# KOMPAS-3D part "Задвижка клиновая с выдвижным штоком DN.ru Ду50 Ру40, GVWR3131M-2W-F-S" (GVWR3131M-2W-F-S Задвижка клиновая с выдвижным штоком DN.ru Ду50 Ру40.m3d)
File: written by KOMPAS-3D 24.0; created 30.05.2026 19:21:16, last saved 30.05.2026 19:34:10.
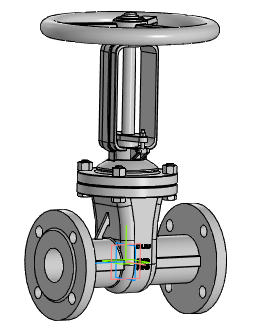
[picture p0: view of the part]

Document properties: Автор: R2D2; Полное имя файла: E:\Работа\Зайцев\GVWR3131M-2W-F-S Задвижка клиновая с выдвижным штоком DN.ru Ду50-100 Ру40\исходные материалы\DN50\GVWR3131M-2W-F-S Задвижка клиновая с выдвижным штоком DN.ru Ду50 Ру40.m3d

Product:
- Component [detail]: Деталь2  | qty 1  | pos. 1  | Автор: R2D2; additional columns: Типовые; source file: Деталь2 Деталь2.m3d
- Component [detail]: AS 1110 - M12 x 45  | qty 4  | pos. 2  | Комментарий: Болты и винты   шестигранные точные   метрические ISO; Автор: R2D2; additional columns: Сталь, мягкая; source file: AS 1110 - M12 x 45 AS 1110 - M12 x 45.m3d
- Component [detail]: ANSI B18.2.4.2M - M12x1,75 - 18  | designation ANSI B18.2.4.2M - M12x1,75  | qty 4  | pos. 3  | Комментарий: Типы метрических   шестигранных гаек   2; Автор: R2D2; additional columns: Сталь, мягкая; source file: ANSI B18.2.4.2M - M12x1,75 ANSI B18.2.4.2M - M12x1,75 - 18.m3d
- Component [detail]: ANSI B18.2.4.2M - M5x0,8 - 8  | designation ANSI B18.2.4.2M - M5x0,8  | qty 1  | pos. 4  | Комментарий: Типы метрических   шестигранных гаек   2; Автор: R2D2; additional columns: Сталь, мягкая; source file: ANSI B18.2.4.2M - M5x0,8 ANSI B18.2.4.2M - M5x0,8 - 8.m3d
- Component [detail]: Деталь1  | qty 1  | pos. 5  | Автор: R2D2; additional columns: Типовые; source file: 2.m3d
- Component [detail]: ФЛАНЕЦ  | designation Деталь1  | qty 1  | pos. 5  | Автор: R2D2; additional columns: Типовые; source file: 1.m3d
- Component [detail]: ФЛАНЕЦ  | designation Деталь1-01  | qty 1  | pos. 6  | Автор: R2D2; additional columns: Типовые; source file: 1.m3d
- Component [detail]: ANSI B18.2.4.2M - M5x0,8 - 8  | designation ANSI B18.2.4.2M - M5x0,8-01  | qty 1  | pos. 7  | Комментарий: Типы метрических   шестигранных гаек   2; Автор: R2D2; additional columns: Сталь, мягкая; source file: ANSI B18.2.4.2M - M5x0,8 ANSI B18.2.4.2M - M5x0,8 - 8.m3d
- Component [detail]: Деталь1  | qty 1  | Автор: R2D2; additional columns: Типовые; source file: 3.m3d
- Body: Тело 1  | qty 1
    Масса: 23.339168
- Part/product: Задвижка клиновая с выдвижным штоком DN.ru Ду50 Ру40  | designation GVWR3131M-2W-F-S
    Масса: 12
    Раздел спецификации: Прочие изделия
    Примечание: D040-08605

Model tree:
1. Массив по концентрической сетке:1  (labels: Грань.Твердое тело1)  (4 pattern instances)
     Шаг 2 = 360
2. Элемент выдавливания:1  (with: Грань.Элемент выдавливания:1, Грань.Элемент вращения:1)
     Расстояние 1 = 42.9933
3. Элемент выдавливания:2  (with: Грань.Элемент выдавливания:1, Грань.Элемент вращения:1)
     Расстояние 1 = 44.6136
4. Элемент выдавливания:3  (with: Грань.Элемент выдавливания:1)
     Расстояние 1 = 54.75
5. Эскиз:1
6. Элемент выдавливания:4  (with: Грань.Элемент выдавливания:1, Грань.Элемент вращения:1)  (labels: Грань.Твердое тело1; Грань.Solid1; Твердое тело1)
     Расстояние 1 = 46; Смещение 1 = 1; Расстояние = -125; Ориентация = 2; Ориентация = 2; Расстояние = -362.5

Referenced files in E:\Работа\Зайцев\GVWR3131M-2W-F-S Задвижка клиновая с выдвижным штоком DN.ru Ду50-100 Ру40\исходные материалы\DN50\: Деталь2 Деталь2.m3d, AS 1110 - M12 x 45 AS 1110 - M12 x 45.m3d, ANSI B18.2.4.2M - M12x1,75 ANSI B18.2.4.2M - M12x1,75 - 18.m3d, ANSI B18.2.4.2M - M5x0,8 ANSI B18.2.4.2M - M5x0,8 - 8.m3d, 2.m3d, 1.m3d, 3.m3d
Referenced files in E:\Работа\Зайцев\GVWR3131M-2W-F-S Задвижка клиновая с выдвижным штоком DN.ru Ду50-200 Ру63\DN50\исходные материалы\: ANSI B18.2.4.2M - M12x1,75 ANSI B18.2.4.2M - M12x1,75 - 18.m3d, AS 1110 - M12 x 45 AS 1110 - M12 x 45.m3d
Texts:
  GVWR3131M-2W-F-S
  DN50
  GOST 26.020 Pr3
  PN40
  Деталь2 Деталь2
  AS 1110 - M12 x 45 AS 1110 - M12 x 45 (1)
  ANSI B18.2.4.2M - M12x1,75 ANSI B18.2.4.2M - M12x1,75 - 18 (1)
  ANSI B18.2.4.2M - M5x0,8 ANSI B18.2.4.2M - M5x0,8 - 8
  Деталь1 Деталь1
  Деталь1 ФЛАНЕЦ
  Деталь1-01 ФЛАНЕЦ
  ANSI B18.2.4.2M - M5x0,8-01 ANSI B18.2.4.2M - M5x0,8 - 8
  Ось Y.Начало координат
  Ось Z.Начало координат
  Плоскость ZX.Начало координат
  Плоскость XY.Начало координат
  Плоскость ZY.Начало координат
  Solid1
